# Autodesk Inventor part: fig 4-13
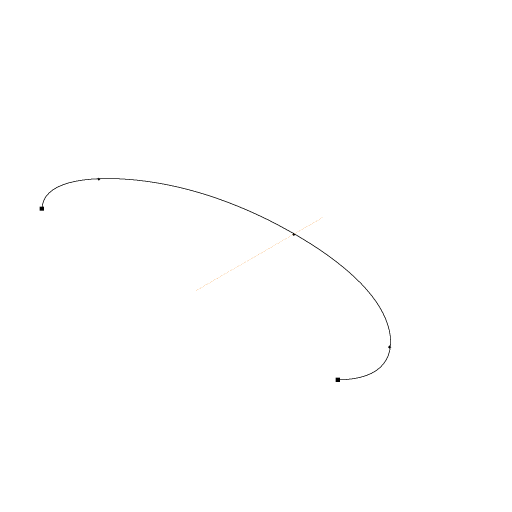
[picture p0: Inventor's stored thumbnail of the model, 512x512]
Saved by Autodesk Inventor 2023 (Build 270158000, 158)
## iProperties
Created: 2012-07
Part Number: fig 4-13
Material: Generic
Document SubType Name: Modeling
Designer: CADCIM
Density: 1 g/cm^3
Appearance: Default
Author: CADCIM
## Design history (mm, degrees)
sketch "Sketch1"
  geometry: L1 (0.121, 13.041)-(0.121, 1.483); L2 (-10.815, -1.576)-(-15.691, 3.573); L3 (-3.522, 10.439)-(3.764, 10.439); L4 (-14.873, 3.848)-(-11.149, 8.074); L5 (11.391, 8.074)-(15.115, 3.848); L6 (15.933, 3.573)-(11.057, -1.576); A1 r 5.401 centre (-9.332, 4.712) between (-14.53, 3.248) and (-11.076, -0.399); A2 r 30.439 centre (0.121, -20) between (3.022, 10.3) and (-2.78, 10.3); A3 r 7.63 centre (-7.286, 0.917) between (-11.348, 7.376) and (-14.205, 4.133); A4 r 7.63 centre (7.528, 0.917) between (14.447, 4.133) and (11.59, 7.376); A5 r 5.401 centre (9.574, 4.712) between (11.318, -0.399) and (14.772, 3.248); 5 further points
  constraints: 12 end point, 10 symmetric about line, 8 midpoint, 5 centre point, 5 point on circle, 1 vertical, 19 other
